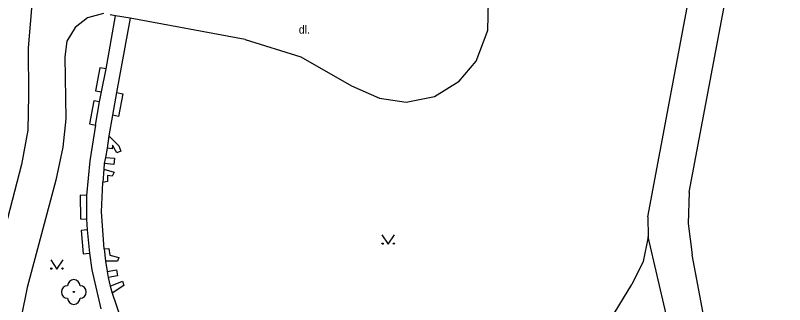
# Model space of a CAD drawing. Extents: x -599951 to -598963, y -1164095 to -1162939.
# Drawn here: x -599806.9 to -599745.1, y -1163330.8 to -1163307.5 of the extents above; entities that cross this region are included whole.
import ezdxf

# ---------------------------------------------------------------- set-up
doc = ezdxf.new("R2010")
doc.units = 0
for name, color, linetype in [('Level 11', 7, 'Continuous'), ('Level 22', 7, 'Continuous'), ('Level 36', 7, 'Continuous'), ('Level 40', 7, 'Continuous'), ('Level 7', 7, 'Continuous')]:
    doc.layers.add(name, color=color, linetype=linetype)

msp = doc.modelspace()

# ---------------------------------------------------------------- linework, layer by layer
at = {"layer": 'Level 11'}
for points in [[(-599756.09, -1163323.74), (-599752.12, -1163302.58)], [(-599752.78, -1163321.76), (-599749.3, -1163303.24), (-599746.93, -1163303.74)], [(-599805.57, -1163306.33), (-599805.88, -1163310.13)], [(-599801.11, -1163307.74), (-599802.09, -1163308.5)], [(-599799.82, -1163307.39), (-599801.11, -1163307.74)], [(-599799.62, -1163311.83), (-599798.85, -1163307.57)], [(-599798.85, -1163307.57), (-599799.28, -1163307.49)], [(-599797.69, -1163307.76), (-599798.85, -1163307.57)], [(-599797.69, -1163307.76), (-599798.77, -1163313.75)], [(-599788.45, -1163309.47), (-599797.69, -1163307.76)], [(-599802.09, -1163308.5), (-599802.78, -1163309.62)], [(-599802.78, -1163309.62), (-599802.94, -1163310.88)], [(-599805.88, -1163310.13), (-599805.84, -1163313.94)], [(-599802.94, -1163310.88), (-599802.86, -1163315.87)], [(-599799.62, -1163311.83), (-599800.11, -1163311.74), (-599800.46, -1163313.61), (-599799.99, -1163313.69)], [(-599799.99, -1163313.69), (-599799.62, -1163311.83)], [(-599805.84, -1163313.94), (-599805.9, -1163316.76)], [(-599800.14, -1163314.49), (-599799.99, -1163313.69)], [(-599798.77, -1163313.75), (-599799.1, -1163315.57)], [(-599798.77, -1163313.75), (-599798.28, -1163313.84), (-599798.61, -1163315.66), (-599799.1, -1163315.57)], [(-599800.14, -1163314.49), (-599800.61, -1163314.4), (-599800.95, -1163316.27), (-599800.46, -1163316.36)], [(-599800.46, -1163316.36), (-599800.14, -1163314.49)], [(-599802.86, -1163315.87), (-599803.09, -1163318.13)], [(-599799.1, -1163315.57), (-599799.39, -1163317.22)], [(-599800.46, -1163316.36), (-599800.91, -1163319.23)], [(-599805.9, -1163316.76), (-599806.42, -1163319.53)], [(-599799.39, -1163317.22), (-599799.53, -1163318.21)], [(-599799.39, -1163317.22), (-599798.75, -1163317.86), (-599798.59, -1163318.02), (-599798.44, -1163318.46), (-599798.76, -1163318.58), (-599799.1, -1163317.98), (-599799.13, -1163318.26), (-599799.53, -1163318.21)], [(-599803.09, -1163318.13), (-599803.66, -1163320.8)], [(-599799.53, -1163318.21), (-599799.67, -1163318.96)], [(-599799.67, -1163318.96), (-599799.77, -1163319.45)], [(-599799.67, -1163318.96), (-599798.95, -1163319.02), (-599799, -1163319.52), (-599799.77, -1163319.45)], [(-599806.42, -1163319.53), (-599808.7, -1163328.23)], [(-599800.91, -1163319.23), (-599801.19, -1163322.02)], [(-599799.77, -1163319.45), (-599799.81, -1163319.92)], [(-599799.81, -1163319.92), (-599799.89, -1163320.98)], [(-599799.81, -1163319.92), (-599798.96, -1163320.14), (-599799.12, -1163320.48), (-599799.51, -1163320.41), (-599799.51, -1163320.9), (-599799.89, -1163320.98)], [(-599803.66, -1163320.8), (-599805.96, -1163329.44)], [(-599799.99, -1163323.34), (-599799.89, -1163320.98)], [(-599801.19, -1163322.02), (-599801.69, -1163322.01), (-599801.68, -1163323.91), (-599801.18, -1163323.92)], [(-599801.19, -1163322.02), (-599801.18, -1163323.92)], [(-599752.78, -1163321.76), (-599752.86, -1163324.29)], [(-599799.77, -1163326.33), (-599799.99, -1163323.34)], [(-599801.18, -1163323.92), (-599801.14, -1163324.78)], [(-599756.09, -1163323.74), (-599756.05, -1163325.34)], [(-599752.86, -1163324.29), (-599752.53, -1163326.8)], [(-599801.14, -1163324.78), (-599801.63, -1163324.84), (-599801.46, -1163326.73), (-599800.96, -1163326.67)], [(-599801.14, -1163324.78), (-599800.96, -1163326.67)], [(-599756.05, -1163325.34), (-599756.46, -1163327.35)], [(-599754.62, -1163331.58), (-599756.05, -1163325.34)], [(-599799.77, -1163326.33), (-599799.4, -1163326.28), (-599799.31, -1163326.84), (-599798.6, -1163327.02), (-599798.69, -1163327.32), (-599799.66, -1163327.32)], [(-599799.77, -1163326.33), (-599799.66, -1163327.32)], [(-599800.96, -1163326.67), (-599800.76, -1163328)], [(-599745.1, -1163366.22), (-599752.53, -1163326.8)], [(-599799.66, -1163327.32), (-599799.53, -1163328.14)], [(-599756.46, -1163327.35), (-599757.38, -1163329.19)], [(-599800.76, -1163328), (-599800.05, -1163331.16)], [(-599799.53, -1163328.14), (-599798.77, -1163328.01), (-599798.69, -1163328.5), (-599799.44, -1163328.63)], [(-599799.53, -1163328.14), (-599799.44, -1163328.63)], [(-599799.44, -1163328.63), (-599799.28, -1163329.32)], [(-599799.28, -1163329.32), (-599798.3, -1163328.93), (-599798.2, -1163329.28), (-599799.13, -1163329.9)], [(-599805.96, -1163329.44), (-599806.45, -1163331.81)], [(-599799.28, -1163329.32), (-599799.13, -1163329.9)], [(-599760.14, -1163333.73), (-599757.38, -1163329.19)], [(-599799.13, -1163329.9), (-599797.75, -1163333.89)]]:
    msp.add_lwpolyline(points, dxfattribs=at)
at = {"layer": 'Level 22'}
msp.add_circle((-599802.21, -1163329.79), 0.05, dxfattribs=at)
for centre, start, end in [((-599802.21, -1163329.29), 0, 180), ((-599802.71, -1163329.79), 90, 270), ((-599801.71, -1163329.79), 270, 90), ((-599802.21, -1163330.29), 180, 0)]:
    msp.add_arc(centre, 0.5, start, end, dxfattribs=at)
at = {"layer": 'Level 36'}
for points in [[(-599777.45, -1163325.2), (-599776.95, -1163325.95), (-599776.45, -1163325.2)], [(-599804.07, -1163327.21), (-599803.57, -1163327.96), (-599803.07, -1163327.21)]]:
    msp.add_lwpolyline(points, dxfattribs=at)
for centre in [(-599777.4, -1163325.9), (-599776.501, -1163325.9), (-599804.02, -1163327.91), (-599803.121, -1163327.91)]:
    msp.add_circle(centre, 0.05, dxfattribs=at)
at = {"layer": 'Level 7'}
for points in [[(-599768.95, -1163308.71), (-599768.89, -1163306.39)], [(-599769.88, -1163311.21), (-599768.99, -1163308.88)], [(-599768.99, -1163308.88), (-599768.95, -1163308.71)], [(-599788.45, -1163309.47), (-599783.98, -1163310.88)], [(-599783.98, -1163310.88), (-599779.91, -1163313.2)], [(-599771.25, -1163312.83), (-599769.88, -1163311.21)], [(-599775.52, -1163314.51), (-599773.22, -1163314.05), (-599771.25, -1163312.83)], [(-599779.91, -1163313.2), (-599777.65, -1163314.2), (-599775.52, -1163314.51)]]:
    msp.add_lwpolyline(points, dxfattribs=at)

# ---------------------------------------------------------------- texts
at = {"layer": 'Level 40'}
msp.add_text('dl.', height=0.65, dxfattribs=at).set_placement((-599784.14, -1163309))

doc.saveas('drawing.dxf')
